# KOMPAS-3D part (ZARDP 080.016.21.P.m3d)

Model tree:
1. Булева операция:1
2. Булева операция:2
3. Булева операция:3
4. Булева операция:4
5. Булева операция:5
6. Булева операция:6
7. Булева операция:7
8. Булева операция:8
9. Булева операция:9
10. Булева операция:10
11. Булева операция:11
12. Булева операция:12
13. Булева операция:13
14. Булева операция:14
15. Булева операция:15
16. Булева операция:16
17. Булева операция:17
18. Булева операция:18
19. Булева операция:19
20. Булева операция:20
21. Булева операция:21
22. Булева операция:23

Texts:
  ЗАРДП 080.016.21-ХХ.Р
  ООО ИК Энерпред-Ярдос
